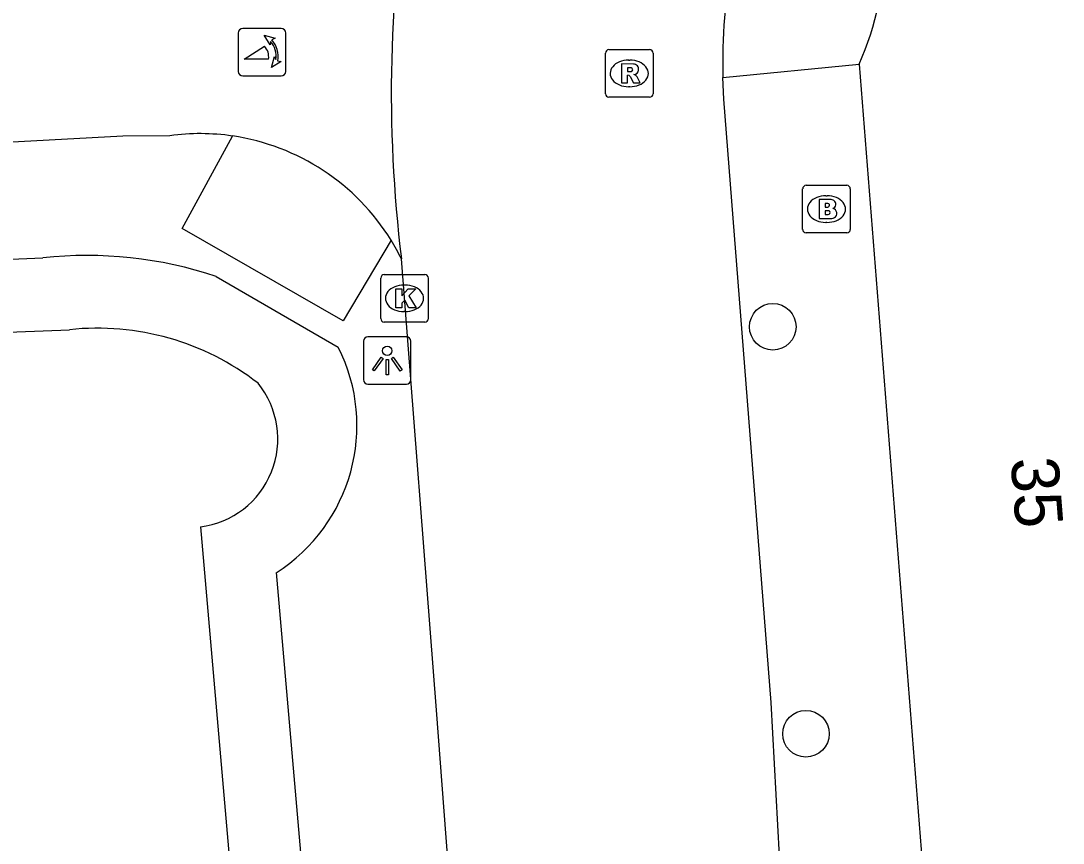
# Model space of a CAD drawing. Extents: x 157793 to 159380, y 380882 to 382313.
# Drawn here: x 157955.99 to 157977.9, y 381429.79 to 381447.07 of the extents above; entities that cross this region are included whole.
import ezdxf

# ---------------------------------------------------------------- set-up
doc = ezdxf.new("R2010")
doc.units = 0
for name, color, linetype in [('IMGEO_Boom', 7, 'Continuous'), ('IMGEO_Brandkraan', 7, 'Continuous'), ('IMGEO_Fietspad_gesloten', 7, 'Continuous'), ('IMGEO_Groenvoorziening', 7, 'Continuous'), ('IMGEO_Kolk', 7, 'Continuous'), ('IMGEO_Lichtpunt', 7, 'Continuous'), ('IMGEO_Pand', 7, 'Continuous'), ('IMGEO_Pand_nummerreeks', 7, 'Continuous'), ('IMGEO_Poller', 7, 'Continuous'), ('IMGEO_Rijbaan_lokaal_gesloten', 7, 'Continuous'), ('IMGEO_Rioolput', 7, 'Continuous'), ('IMGEO_Voetpad_halfverhard', 7, 'Continuous'), ('IMGEO_Voetpad_open', 7, 'Continuous'), ('IMGEO_Waterloop', 7, 'Continuous')]:
    doc.layers.add(name, color=color, linetype=linetype)

msp = doc.modelspace()

# ---------------------------------------------------------------- linework, layer by layer
at = {"layer": 'IMGEO_Boom'}
for centre in [(157971.795, 381440.642), (157972.492, 381432.089)]:
    msp.add_circle(centre, 0.489, dxfattribs=at)
at = {"layer": 'IMGEO_Brandkraan'}
for p, q in [((157972.498, 381443.614), (157973.35, 381443.614)), ((157972.423, 381442.688), (157972.423, 381443.54)), ((157972.911, 381443.394), (157972.936, 381443.394)), ((157973.424, 381443.54), (157973.424, 381442.688)), ((157972.934, 381442.834), (157972.909, 381442.834)), ((157973.35, 381442.614), (157972.498, 381442.614))]:
    msp.add_line(p, q, dxfattribs=at)
for points in [[(157972.498, 381443.614), (157973.35, 381443.614)], [(157972.423, 381442.688), (157972.423, 381443.54)], [(157973.424, 381443.54), (157973.424, 381442.688)], [(157972.771, 381443.314), (157972.771, 381442.914), (157972.984, 381442.914)], [(157973.002, 381443.314), (157972.771, 381443.314)], [(157972.95, 381443.233), (157972.896, 381443.233), (157972.896, 381443.157)], [(157972.896, 381443.157), (157972.949, 381443.157)], [(157972.958, 381443.081), (157972.896, 381443.081), (157972.896, 381443)], [(157972.896, 381443), (157972.958, 381443)], [(157973.35, 381442.614), (157972.498, 381442.614)]]:
    msp.add_lwpolyline(points, dxfattribs=at)
for centre, radius, start, end in [((157972.5, 381443.538), 0.0765, 91.552, 178.448), ((157972.5, 381443.538), 0.0765, 91.552, 178.448), ((157973.348, 381443.538), 0.0765, 1.552, 88.448), ((157973.348, 381443.538), 0.0765, 1.552, 88.448), ((157972.951, 381443.195), 0.0379, 267.8285, 90.9355), ((157973.006, 381443.169), 0.145, 59.4692, 91.5367), ((157973.031, 381443.216), 0.0922, 285.5137, 58.1501), ((157973.036, 381443.024), 0.105, 301.3115, 78.989), ((157972.959, 381443.04), 0.0404, 269.8759, 90.5077), ((157972.99, 381443.165), 0.251, 268.6676, 293.5347), ((157972.5, 381442.69), 0.0765, 181.552, 268.448), ((157972.5, 381442.69), 0.0765, 181.552, 268.448), ((157973.348, 381442.69), 0.0765, 271.552, 358.448), ((157973.348, 381442.69), 0.0765, 271.552, 358.448)]:
    msp.add_arc(centre, radius, start, end, dxfattribs=at)
for centre, major_axis, ratio, start_param, end_param in [((157972.91, 381443.114), (-0.387, 0.002), 0.722429, 4.712389, 7.853982), ((157972.935, 381443.114), (-0.39, 0.002), 0.717154, 1.570796, 4.712389)]:
    msp.add_ellipse(centre, major_axis=major_axis, ratio=ratio, start_param=start_param, end_param=end_param, dxfattribs=at)
at = {"layer": 'IMGEO_Fietspad_gesloten'}
msp.add_lwpolyline([(157959.125, 381444.657), (157958.138, 381444.645), (157951.294, 381444.278)], dxfattribs=at)
for centre, radius, start, end in [((157959.758, 381440.021), 4.679, 81.6109, 97.7796), ((157959.757, 381439.981), 4.719, 31.7072, 81.6702), ((157959.733, 381439.969), 4.746, 26.2367, 31.6748)]:
    msp.add_arc(centre, radius, start, end, dxfattribs=at)
at = {"layer": 'IMGEO_Groenvoorziening'}
for points in [[(157947.53, 381441.718), (157956.453, 381442.091)], [(157960.099, 381441.699), (157961.729, 381440.754), (157962.663, 381440.213)], [(157961.356, 381435.474), (157962.76, 381419.356), (157963.785, 381405.488)]]:
    msp.add_lwpolyline(points, dxfattribs=at)
for centre, radius, start, end in [((157957.372, 381433.487), 8.653, 71.6298, 96.097), ((157959.397, 381438.564), 3.659, 302.3771, 26.7855)]:
    msp.add_arc(centre, radius, start, end, dxfattribs=at)
at = {"layer": 'IMGEO_Kolk'}
for p, q in [((157963.555, 381440.813), (157963.555, 381441.665)), ((157963.63, 381441.739), (157964.482, 381441.739)), ((157964.556, 381441.665), (157964.556, 381440.813)), ((157964.043, 381441.519), (157964.068, 381441.519)), ((157964.066, 381440.959), (157964.041, 381440.959)), ((157964.482, 381440.739), (157963.63, 381440.739))]:
    msp.add_line(p, q, dxfattribs=at)
for points in [[(157963.555, 381440.813), (157963.555, 381441.665)], [(157963.63, 381441.739), (157964.482, 381441.739)], [(157964.556, 381441.665), (157964.556, 381440.813)], [(157963.876, 381441.439), (157963.999, 381441.439), (157963.999, 381441.288), (157964.129, 381441.439), (157964.293, 381441.439), (157964.147, 381441.288), (157964.3, 381441.039), (157964.148, 381441.039), (157964.063, 381441.203), (157963.999, 381441.136), (157963.999, 381441.039), (157963.876, 381441.039), (157963.876, 381441.439)], [(157964.482, 381440.739), (157963.63, 381440.739)]]:
    msp.add_lwpolyline(points, dxfattribs=at)
for centre, start, end in [((157963.632, 381441.663), 91.552, 178.448), ((157963.632, 381441.663), 91.552, 178.448), ((157964.48, 381441.663), 1.552, 88.448), ((157964.48, 381441.663), 1.552, 88.448), ((157963.632, 381440.815), 181.552, 268.448), ((157963.632, 381440.815), 181.552, 268.448), ((157964.48, 381440.815), 271.552, 358.448), ((157964.48, 381440.815), 271.552, 358.448)]:
    msp.add_arc(centre, 0.0765, start, end, dxfattribs=at)
for centre, major_axis, ratio, start_param, end_param in [((157964.042, 381441.239), (-0.387, 0.002), 0.722429, 4.712389, 7.853982), ((157964.067, 381441.239), (-0.39, 0.002), 0.717154, 1.570796, 4.712389)]:
    msp.add_ellipse(centre, major_axis=major_axis, ratio=ratio, start_param=start_param, end_param=end_param, dxfattribs=at)
at = {"layer": 'IMGEO_Lichtpunt'}
for p, q in [((157963.194, 381440.338), (157963.194, 381439.531)), ((157963.194, 381440.338), (157963.194, 381439.531)), ((157964.096, 381440.433), (157963.288, 381440.433)), ((157964.096, 381440.433), (157963.288, 381440.433)), ((157964.19, 381439.531), (157964.19, 381440.338)), ((157964.19, 381439.531), (157964.19, 381440.338)), ((157963.288, 381439.437), (157964.096, 381439.437)), ((157963.288, 381439.437), (157964.096, 381439.437))]:
    msp.add_line(p, q, dxfattribs=at)
for points in [[(157963.568, 381440.002), (157963.607, 381439.974), (157963.419, 381439.712), (157963.381, 381439.739), (157963.568, 381440.002)], [(157963.67, 381439.954), (157963.717, 381439.954), (157963.717, 381439.632), (157963.67, 381439.632), (157963.67, 381439.954)], [(157963.78, 381439.974), (157963.818, 381440.001), (157964.005, 381439.739), (157963.966, 381439.711), (157963.78, 381439.974)]]:
    msp.add_lwpolyline(points, dxfattribs=at)
msp.add_circle((157963.693, 381440.136), 0.0994, dxfattribs=at)
for centre, start, end in [((157963.288, 381440.338), 90, 180), ((157963.288, 381440.338), 90, 180), ((157964.096, 381440.338), 0, 90), ((157964.096, 381440.338), 0, 90), ((157963.288, 381439.531), 180, 270), ((157963.288, 381439.531), 180, 270), ((157964.096, 381439.531), 270, 0), ((157964.096, 381439.531), 270, 360)]:
    msp.add_arc(centre, 0.0946, start, end, dxfattribs=at)
at = {"layer": 'IMGEO_Pand'}
msp.add_lwpolyline([(157973.61, 381446.16), (157975.08, 381427.53)], dxfattribs=at)
msp.add_arc((157968.143, 381448.609), 5.991, 335.8732, 1.2075, dxfattribs=at)
at = {"layer": 'IMGEO_Poller'}
for p, q in [((157961.464, 381446.908), (157960.656, 381446.908)), ((157961.464, 381446.908), (157960.656, 381446.908)), ((157960.562, 381446.813), (157960.562, 381446.006)), ((157960.562, 381446.813), (157960.562, 381446.006)), ((157961.558, 381446.006), (157961.558, 381446.813)), ((157961.558, 381446.006), (157961.558, 381446.813)), ((157960.656, 381445.911), (157961.464, 381445.911)), ((157960.656, 381445.911), (157961.464, 381445.911))]:
    msp.add_line(p, q, dxfattribs=at)
for points in [[(157961.241, 381446.637), (157961.229, 381446.564), (157961.104, 381446.769)], [(157961.104, 381446.769), (157961.335, 381446.703), (157961.264, 381446.671)], [(157961.197, 381446.264), (157960.684, 381446.264), (157961.114, 381446.539)], [(157961.257, 381446.092), (157961.323, 381446.323), (157961.353, 381446.255)], [(157961.389, 381446.228), (157961.461, 381446.217), (157961.257, 381446.092)]]:
    msp.add_lwpolyline(points, dxfattribs=at)
for centre, radius, start, end in [((157960.656, 381446.813), 0.0946, 90, 180), ((157960.656, 381446.813), 0.0946, 90, 180), ((157961.464, 381446.813), 0.0946, 0, 90), ((157961.464, 381446.813), 0.0946, 0, 90), ((157960.883, 381446.324), 0.476, 351.7527, 41.1691), ((157960.883, 381446.324), 0.516, 349.3569, 42.2912), ((157960.869, 381446.314), 0.332, 351.3247, 42.4854), ((157960.656, 381446.006), 0.0946, 180, 270), ((157960.656, 381446.006), 0.0946, 180, 270), ((157961.464, 381446.006), 0.0946, 270, 0), ((157961.464, 381446.006), 0.0946, 270, 0)]:
    msp.add_arc(centre, radius, start, end, dxfattribs=at)
at = {"layer": 'IMGEO_Rijbaan_lokaal_gesloten'}
for points in [[(157975.516, 381383.424), (157975.082, 381388.727), (157974.481, 381396.457), (157972.816, 381417.811), (157972.04, 381427.592), (157971.761, 381432.744), (157970.763, 381445.421), (157970.745, 381445.878)], [(157967.719, 381393.481), (157967.27, 381399.085), (157964.731, 381432.587), (157963.99, 381442.067)]]:
    msp.add_lwpolyline(points, dxfattribs=at)
for centre, radius, start, end in [((157983.857, 381446.159), 13.115, 159.2464, 181.2262), ((157992.882, 381445.573), 29.104, 170.3955, 186.9191)]:
    msp.add_arc(centre, radius, start, end, dxfattribs=at)
at = {"layer": 'IMGEO_Rioolput'}
for p, q in [((157968.353, 381446.465), (157969.205, 381446.465)), ((157968.278, 381445.539), (157968.278, 381446.391)), ((157968.766, 381446.245), (157968.791, 381446.245)), ((157969.279, 381446.391), (157969.279, 381445.539)), ((157968.789, 381445.685), (157968.764, 381445.685)), ((157969.205, 381445.465), (157968.353, 381445.465))]:
    msp.add_line(p, q, dxfattribs=at)
for points in [[(157968.353, 381446.465), (157969.205, 381446.465)], [(157968.278, 381445.539), (157968.278, 381446.391)], [(157969.279, 381446.391), (157969.279, 381445.539)], [(157968.867, 381446.163), (157968.615, 381446.165), (157968.615, 381445.765)], [(157968.793, 381446.084), (157968.739, 381446.084), (157968.739, 381446.003)], [(157968.739, 381446.003), (157968.791, 381446.003)], [(157968.615, 381445.765), (157968.739, 381445.765), (157968.739, 381445.927), (157968.75, 381445.927)], [(157968.797, 381445.898), (157968.868, 381445.765), (157969.008, 381445.765), (157968.943, 381445.891)], [(157969.205, 381445.465), (157968.353, 381445.465)]]:
    msp.add_lwpolyline(points, dxfattribs=at)
for centre, radius, start, end in [((157968.355, 381446.389), 0.0765, 91.552, 178.448), ((157968.355, 381446.389), 0.0765, 91.552, 178.448), ((157969.203, 381446.389), 0.0765, 1.552, 88.448), ((157969.203, 381446.389), 0.0765, 1.552, 88.448), ((157968.775, 381446.192), 0.19, 274.7715, 282.9687), ((157968.799, 381445.988), 0.0964, 77.0061, 93.1865), ((157968.813, 381446.045), 0.0378, 276.6634, 79.6772), ((157968.866, 381446.053), 0.109, 350.3612, 89.416), ((157968.864, 381446.053), 0.112, 277.5842, 350.9817), ((157968.749, 381445.874), 0.0533, 26.0293, 88.6989), ((157968.848, 381445.838), 0.108, 29.5134, 73.7905), ((157968.355, 381445.541), 0.0765, 181.552, 268.448), ((157968.355, 381445.541), 0.0765, 181.552, 268.448), ((157969.203, 381445.541), 0.0765, 271.552, 358.448), ((157969.203, 381445.541), 0.0765, 271.552, 358.448)]:
    msp.add_arc(centre, radius, start, end, dxfattribs=at)
for centre, major_axis, ratio, start_param, end_param in [((157968.765, 381445.965), (-0.387, 0.002), 0.722429, 4.712389, 7.853982), ((157968.79, 381445.965), (-0.39, 0.002), 0.717154, 1.570796, 4.712389)]:
    msp.add_ellipse(centre, major_axis=major_axis, ratio=ratio, start_param=start_param, end_param=end_param, dxfattribs=at)
at = {"layer": 'IMGEO_Voetpad_halfverhard'}
msp.add_lwpolyline([(157963.772, 381442.461), (157962.764, 381440.764), (157959.384, 381442.709), (157960.441, 381444.65)], dxfattribs=at)
at = {"layer": 'IMGEO_Voetpad_open'}
msp.add_lwpolyline([(157970.745, 381445.878), (157973.61, 381446.16)], dxfattribs=at)
at = {"layer": 'IMGEO_Waterloop'}
for points in [[(157947.593, 381440.219), (157957.018, 381440.58)], [(157959.766, 381436.437), (157961.369, 381417.989), (157962.275, 381405.51), (157962.27, 381405.358)]]:
    msp.add_lwpolyline(points, dxfattribs=at)
for centre, radius, start, end in [((157957.603, 381435.106), 5.505, 52.2013, 96.0991), ((157959.529, 381438.284), 1.863, 277.3092, 38.9768)]:
    msp.add_arc(centre, radius, start, end, dxfattribs=at)

# ---------------------------------------------------------------- texts
at = {"layer": 'IMGEO_Pand_nummerreeks'}
msp.add_text('35', height=1, rotation=274.5116, dxfattribs=at).set_placement((157976.792, 381437.867))

doc.saveas('drawing.dxf')
